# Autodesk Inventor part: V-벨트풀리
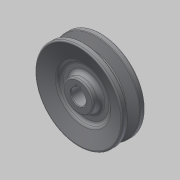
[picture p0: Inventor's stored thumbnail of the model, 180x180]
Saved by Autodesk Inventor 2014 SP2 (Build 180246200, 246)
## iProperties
Created: 2016-08
Part Number: V-벨트풀리
Material: 알루미늄 6061
Document SubType Name: Modeling
Designer: mduedu
Density: 2.71 g/cm^3
Appearance: 기본값
Author: mduedu
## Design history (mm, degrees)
sketch "스케치1"
  geometry: L1 (0, 9.5)-(0, -9.5); L2 (0, 9.5)-(35, 9.5); L3 (35, 9.5)-(35, 4.825); L4 (35, 4.825)-(26, 2.074); L5 (26, 2.074)-(26, 0); L6 (0, 0)-(26, 0); L7 (0, -9.5)-(35, -9.5); L8 (35, -9.5)-(35, -4.825); L9 (35, -4.825)-(26, -2.074); L10 (26, -2.074)-(26, 0); L11 (32.3, 9.5)-(32.3, -9.5); 3 further points
  constraints: 22 end point, 6 point on line, 4 perpendicular, 3 symmetric about line, 1 coincident, 1 horizontal alignment, 1 midpoint, 1 parallel, 1 vertical
  dimensions: "d0" = 19 distance of L1.start L1.end; "d2" = 70 diameter of L8 L1; "d4" = 6.3 distance between parallel lines of L10 L11; "d5" = 2.7 distance between parallel lines of L11 L8; "d6" = 8 distance of point (32.3, -4) point (32.3, 4); "d7" = 34 deg angle of L9 L4
revolve "회전1" sketch "스케치1" stored, may be unused: angle "d8" = 90 deg
sketch "스케치2"
  geometry: L1 (-2, 0)-(2, 0); L2 (2, 0)-(2, 7.8); L3 (2, 7.8)-(-2, 7.8); L4 (-2, 7.8)-(-2, 0); C1 r 6 at (0, 0); 2 further points
  constraints: 8 end point, 2 coincident, 2 parallel, 1 centre point, 1 horizontal, 1 midpoint, 1 perpendicular
  dimensions: "d9" = 12 diameter of C1; "d11" = 4 distance of L2.end L3.end; "d12" = 7.8 distance of L1.end L2.end
extrude "돌출1" cut sketch "스케치2" stored distance "d13" = 10; taper "d14" = 0 deg
sketch "스케치3"
  geometry: L1 (35, 4.825)-(26, 2.074) reference; L2 (26, 2.074)-(26, -2.074) reference; L3 (0, 0)-(26, 0); L4 (35, 9.5)-(35, 4.825) reference; L5 (-35, 9.5)-(35, 9.5) reference; L6 (35, 9.5)-(21, 5.22); L7 (21, 5.22)-(21, 3); L8 (21, 3)-(12, 3); L9 (12, 3)-(12, 9.5); L10 (0, 9.5)-(0, -9.5); L11 (5.657, -9.5)-(-6, -9.5) reference; L12 (12, 9.5)-(35, 9.5)
  constraints: 14 end point, 3 midpoint, 2 parallel, 2 perpendicular, 2 point on line, 1 collinear, 1 horizontal
  dimensions: "d15" = 3 distance between parallel lines of L3 L8; "d17" = 42 diameter of L7 L10; "d18" = 24 diameter of L9 L10
revolve "회전2" sketch "스케치3" stored, may be unused: angle "d19" = 90 deg
fillet "모깎기1" dims "d20" = 0.5, "d21" = 1, "d22" = 1
fillet "모깎기2" dims "d23" = 3
fillet "모깎기3" dims "d24" = 3
fillet "모깎기4" dims "d25" = 3
chamfer "모따기1" distance "d26" = 0.5; stored, may be unused: second distance "d27" = 2, angle "d28" = 45 deg
fillet "모깎기5" dims "d29" = 1
node "솔리드1"
mirror "대칭1"
